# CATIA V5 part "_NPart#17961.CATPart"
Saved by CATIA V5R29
Part number: kap?
Revision: HERHANG?
Definition: B??MEYEN
Nomenclature: kap?
Source: Unknown
Bounding box of the stored display mesh (mm): x -530.255 to 530.255, y -530.179 to 530.179, z -206.95 to 40
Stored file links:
  C:\가치같이\SmartFactory_Freeze dryer\_NPart#17961.CATPart
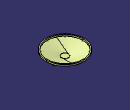
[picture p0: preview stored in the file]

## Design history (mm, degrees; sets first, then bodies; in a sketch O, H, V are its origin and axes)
Set1
  DatumSurface1 to DatumSurface4 "NONE"
Body1 (main body)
